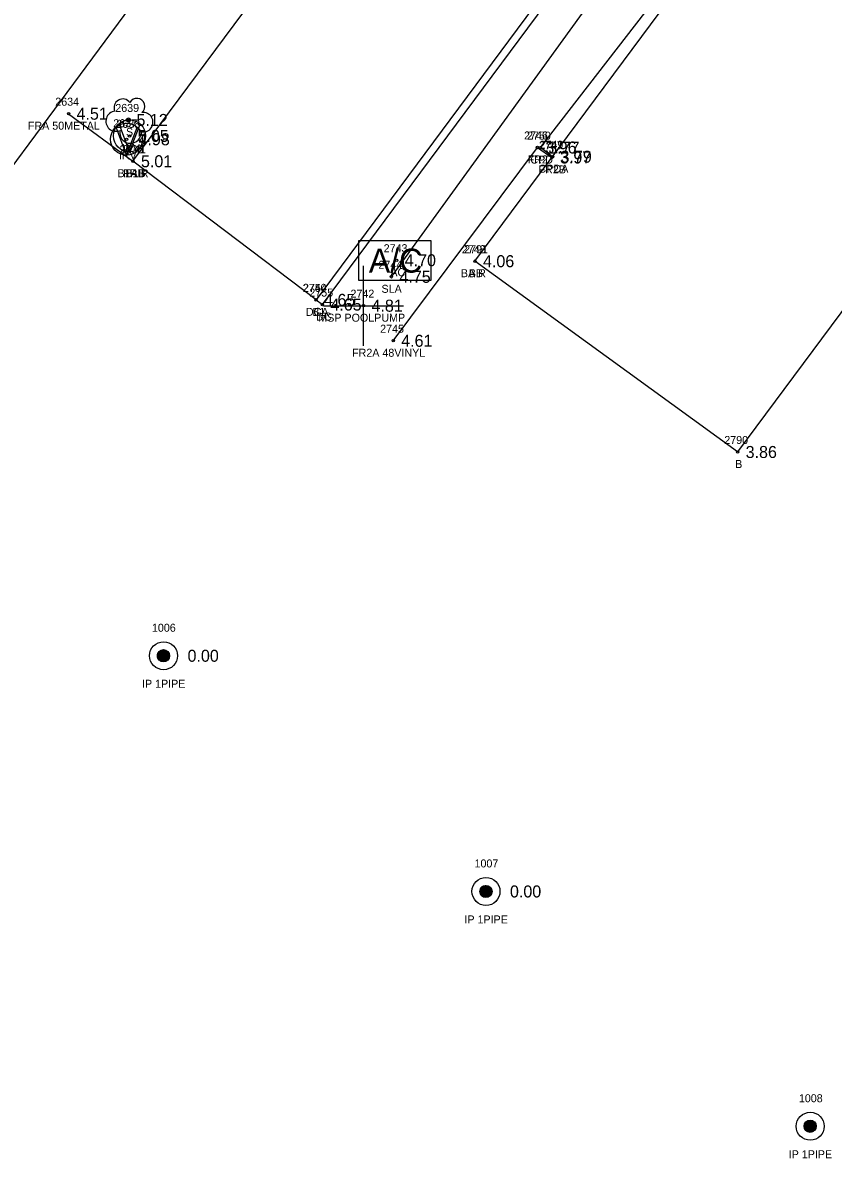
# Model space of a CAD drawing. Extents: x 2608598 to 2610682, y 641451 to 643526.
# Drawn here: x 2610061 to 2610162.3, y 641830.4 to 641972.3 of the extents above; entities that cross this region are included whole.
import ezdxf

# ---------------------------------------------------------------- set-up
doc = ezdxf.new("R2010")
doc.units = 0
for name, color, linetype in [('RD_EX_Bldg', 7, 'Continuous'), ('RD_EX_Bldg_txCode', 7, 'Continuous'), ('RD_EX_BldgApp', 7, 'Continuous'), ('RD_EX_BldgApp_txCode', 7, 'Continuous'), ('RD_EX_Conc', 7, 'Continuous'), ('RD_EX_Conc_txCode', 7, 'Continuous'), ('RD_EX_DV_Prop_txCode', 7, 'Continuous'), ('RD_EX_DV_PropPin', 7, 'Continuous'), ('RD_EX_Fence_Other', 7, 'Continuous'), ('RD_EX_Fence_Other_txCode', 7, 'Continuous'), ('RD_EX_Misc', 7, 'Continuous'), ('RD_EX_Misc_txCode', 7, 'Continuous'), ('RD_EX_TX_Bldg_ELEV', 7, 'Continuous'), ('RD_EX_TX_BldgApp_ELEV', 7, 'Continuous'), ('RD_EX_TX_Conc_ELEV', 7, 'Continuous'), ('RD_EX_TX_DV_Prop_ELEV', 7, 'Continuous'), ('RD_EX_TX_Fence_Other_ELEV', 7, 'Continuous'), ('RD_EX_TX_Misc_ELEV', 7, 'Continuous'), ('RD_EX_TX_UT_ELEV', 7, 'Continuous'), ('RD_EX_TX_VEG_ELEV', 7, 'Continuous'), ('RD_EX_UT', 7, 'Continuous'), ('RD_EX_UT_txCode', 7, 'Continuous'), ('RD_EX_VEG', 7, 'Continuous'), ('RD_EX_VEG_txCode', 7, 'Continuous'), ('RD_SMD_Locator', 7, 'Continuous')]:
    doc.layers.add(name, color=color, linetype=linetype)

msp = doc.modelspace()

# ---------------------------------------------------------------- linework, layer by layer
at = {"layer": 'RD_EX_Bldg'}
for points in [[(2610074.75, 641955.02), (2610121.89, 642018.49), (2610144.77, 642001.17), (2610097.63, 641937.7), (2610074.75, 641955.02)], [(2610117.49, 641942.53), (2610163.78, 642004.89), (2610174.8, 641996.67), (2610165.23, 641983.77), (2610177.63, 641974.57), (2610167.76, 641961.77), (2610177.2, 641954.91), (2610150.31, 641918.69), (2610117.49, 641942.53)], [(2610055.59, 641998.42), (2610028.78, 641961.42), (2610024.2, 641964.93), (2610014.46, 641951.93), (2610030.09, 641940.65), (2610042.73, 641931.52), (2610079.25, 641980.82), (2610055.59, 641998.42)]]:
    msp.add_lwpolyline(points, dxfattribs=at)
at = {"layer": 'RD_EX_BldgApp'}
for q in [(2610072.64, 641959.26), (2610075.27, 641959.22)]:
    msp.add_line((2610073.95, 641955.77), q, dxfattribs=at)
msp.add_lwpolyline([(2610102.97, 641940.1), (2610102.97, 641945.1), (2610111.97, 641945.1), (2610111.97, 641940.1)], close=True, dxfattribs=at)
for radius in [2, 0.15]:
    msp.add_circle((2610073.95, 641957.77), radius, dxfattribs=at)
at = {"layer": 'RD_EX_Conc'}
for points in [[(2610097.63, 641937.7), (2610098.42, 641937.11), (2610146.5, 642001.85), (2610145.19, 642002.76), (2610160.49, 642023.46), (2610172.05, 642039.3)], [(2610127.18, 641955.59), (2610125.66, 641956.72), (2610143.6, 641979.88), (2610144.54, 641978.98)]]:
    msp.add_lwpolyline(points, dxfattribs=at)
at = {"layer": 'RD_EX_DV_PropPin'}
for p, q in [((2610077.83, 641893.03), (2610077.83, 641893.42)), ((2610077.87, 641892.93), (2610077.87, 641893.52)), ((2610077.9, 641892.86), (2610077.9, 641893.6)), ((2610077.94, 641892.8), (2610077.94, 641893.65)), ((2610077.97, 641892.75), (2610077.97, 641893.7)), ((2610078.01, 641892.71), (2610078.01, 641893.74)), ((2610078.04, 641892.68), (2610078.04, 641893.78)), ((2610078.08, 641892.64), (2610078.08, 641893.81)), ((2610078.11, 641892.62), (2610078.11, 641893.84)), ((2610078.15, 641892.59), (2610078.15, 641893.86)), ((2610078.18, 641892.57), (2610078.18, 641893.88)), ((2610078.22, 641892.55), (2610078.22, 641893.9)), ((2610078.25, 641892.53), (2610078.25, 641893.92)), ((2610078.29, 641892.52), (2610078.29, 641893.93)), ((2610078.32, 641892.51), (2610078.32, 641893.95)), ((2610078.36, 641892.49), (2610078.36, 641893.96)), ((2610078.39, 641892.49), (2610078.39, 641893.97)), ((2610078.43, 641892.48), (2610078.43, 641893.97)), ((2610078.46, 641892.47), (2610078.46, 641893.98)), ((2610078.5, 641892.47), (2610078.5, 641893.98)), ((2610078.53, 641892.47), (2610078.53, 641893.99)), ((2610078.57, 641892.47), (2610078.57, 641893.99)), ((2610078.6, 641892.47), (2610078.6, 641893.99)), ((2610078.64, 641892.47), (2610078.64, 641893.98)), ((2610078.67, 641892.47), (2610078.67, 641893.98)), ((2610078.71, 641892.48), (2610078.71, 641893.97)), ((2610078.74, 641892.49), (2610078.74, 641893.97)), ((2610078.78, 641892.49), (2610078.78, 641893.96)), ((2610078.81, 641892.51), (2610078.81, 641893.95)), ((2610078.85, 641892.52), (2610078.85, 641893.93)), ((2610078.88, 641892.53), (2610078.88, 641893.92)), ((2610078.92, 641892.55), (2610078.92, 641893.9)), ((2610078.95, 641892.57), (2610078.95, 641893.88)), ((2610078.99, 641892.59), (2610078.99, 641893.86)), ((2610079.02, 641892.62), (2610079.02, 641893.84)), ((2610079.06, 641892.64), (2610079.06, 641893.81)), ((2610079.09, 641892.68), (2610079.09, 641893.78)), ((2610079.13, 641892.71), (2610079.13, 641893.74)), ((2610079.16, 641892.75), (2610079.16, 641893.7)), ((2610079.2, 641892.8), (2610079.2, 641893.65)), ((2610079.23, 641892.86), (2610079.23, 641893.6)), ((2610079.27, 641892.93), (2610079.27, 641893.52)), ((2610079.3, 641893.03), (2610079.3, 641893.42)), ((2610118.68, 641863.04), (2610118.68, 641864.53)), ((2610118.72, 641863.04), (2610118.72, 641864.53)), ((2610118.75, 641863.03), (2610118.75, 641864.54)), ((2610118.79, 641863.03), (2610118.79, 641864.54)), ((2610118.82, 641863.02), (2610118.82, 641864.54)), ((2610118.86, 641863.02), (2610118.86, 641864.55)), ((2610118.89, 641863.02), (2610118.89, 641864.54)), ((2610118.93, 641863.03), (2610118.93, 641864.54)), ((2610118.96, 641863.03), (2610118.96, 641864.54)), ((2610119, 641863.04), (2610119, 641864.53)), ((2610119.03, 641863.04), (2610119.03, 641864.53)), ((2610118.12, 641863.59), (2610118.12, 641863.98)), ((2610118.16, 641863.49), (2610118.16, 641864.08)), ((2610118.19, 641863.42), (2610118.19, 641864.15)), ((2610118.23, 641863.36), (2610118.23, 641864.21)), ((2610118.26, 641863.31), (2610118.26, 641864.26)), ((2610118.3, 641863.27), (2610118.3, 641864.3)), ((2610118.33, 641863.23), (2610118.33, 641864.34)), ((2610118.37, 641863.2), (2610118.37, 641864.37)), ((2610118.4, 641863.17), (2610118.4, 641864.39)), ((2610118.44, 641863.15), (2610118.44, 641864.42)), ((2610118.47, 641863.13), (2610118.47, 641864.44)), ((2610118.51, 641863.11), (2610118.51, 641864.46)), ((2610118.54, 641863.09), (2610118.54, 641864.48)), ((2610118.58, 641863.08), (2610118.58, 641864.49)), ((2610118.61, 641863.06), (2610118.61, 641864.51)), ((2610118.65, 641863.05), (2610118.65, 641864.52)), ((2610119.07, 641863.05), (2610119.07, 641864.52)), ((2610119.1, 641863.06), (2610119.1, 641864.51)), ((2610119.14, 641863.08), (2610119.14, 641864.49)), ((2610119.17, 641863.09), (2610119.17, 641864.48)), ((2610119.21, 641863.11), (2610119.21, 641864.46)), ((2610119.24, 641863.13), (2610119.24, 641864.44)), ((2610119.28, 641863.15), (2610119.28, 641864.42)), ((2610119.31, 641863.17), (2610119.31, 641864.39)), ((2610119.35, 641863.2), (2610119.35, 641864.37)), ((2610119.38, 641863.23), (2610119.38, 641864.34)), ((2610119.42, 641863.27), (2610119.42, 641864.3)), ((2610119.45, 641863.31), (2610119.45, 641864.26)), ((2610119.49, 641863.36), (2610119.49, 641864.21)), ((2610119.52, 641863.42), (2610119.52, 641864.15)), ((2610119.56, 641863.49), (2610119.56, 641864.08)), ((2610119.59, 641863.59), (2610119.59, 641863.98)), ((2610158.68, 641834.14), (2610158.68, 641834.73)), ((2610158.72, 641834.07), (2610158.72, 641834.81)), ((2610158.75, 641834.01), (2610158.75, 641834.86)), ((2610158.79, 641833.96), (2610158.79, 641834.91)), ((2610158.82, 641833.92), (2610158.82, 641834.95)), ((2610158.86, 641833.89), (2610158.86, 641834.99)), ((2610158.89, 641833.85), (2610158.89, 641835.02)), ((2610158.93, 641833.83), (2610158.93, 641835.05)), ((2610158.96, 641833.8), (2610158.96, 641835.07)), ((2610159, 641833.78), (2610159, 641835.09)), ((2610159.03, 641833.76), (2610159.03, 641835.11)), ((2610159.07, 641833.74), (2610159.07, 641835.13)), ((2610159.1, 641833.73), (2610159.1, 641835.14)), ((2610159.14, 641833.72), (2610159.14, 641835.16)), ((2610159.17, 641833.7), (2610159.17, 641835.17)), ((2610159.21, 641833.7), (2610159.21, 641835.18)), ((2610159.24, 641833.69), (2610159.24, 641835.18)), ((2610159.28, 641833.68), (2610159.28, 641835.19)), ((2610159.31, 641833.68), (2610159.31, 641835.19)), ((2610159.35, 641833.68), (2610159.35, 641835.2)), ((2610159.38, 641833.68), (2610159.38, 641835.2)), ((2610159.42, 641833.68), (2610159.42, 641835.2)), ((2610159.45, 641833.68), (2610159.45, 641835.19)), ((2610159.49, 641833.68), (2610159.49, 641835.19)), ((2610159.52, 641833.69), (2610159.52, 641835.18)), ((2610159.56, 641833.7), (2610159.56, 641835.18)), ((2610159.59, 641833.7), (2610159.59, 641835.17)), ((2610159.63, 641833.72), (2610159.63, 641835.16)), ((2610159.66, 641833.73), (2610159.66, 641835.14)), ((2610159.7, 641833.74), (2610159.7, 641835.13)), ((2610159.73, 641833.76), (2610159.73, 641835.11)), ((2610159.77, 641833.78), (2610159.77, 641835.09)), ((2610159.8, 641833.8), (2610159.8, 641835.07)), ((2610159.84, 641833.83), (2610159.84, 641835.05)), ((2610159.87, 641833.85), (2610159.87, 641835.02)), ((2610159.91, 641833.89), (2610159.91, 641834.99)), ((2610159.94, 641833.92), (2610159.94, 641834.95)), ((2610159.98, 641833.96), (2610159.98, 641834.91)), ((2610160.01, 641834.01), (2610160.01, 641834.86)), ((2610160.05, 641834.07), (2610160.05, 641834.81)), ((2610160.08, 641834.14), (2610160.08, 641834.73)), ((2610158.65, 641834.24), (2610158.65, 641834.63)), ((2610160.12, 641834.24), (2610160.12, 641834.63))]:
    msp.add_line(p, q, dxfattribs=at)
for centre, radius in [((2610078.57, 641893.23), 1.75), ((2610078.57, 641893.23), 0.761), ((2610118.86, 641863.78), 1.75), ((2610118.86, 641863.78), 0.761), ((2610159.38, 641834.44), 1.75), ((2610159.38, 641834.44), 0.761)]:
    msp.add_circle(centre, radius, dxfattribs=at)
at = {"layer": 'RD_EX_Fence_Other'}
msp.add_line((2610066.7, 641960.96), (2610074.75, 641955.02), dxfattribs=at)
msp.add_lwpolyline([(2610107.27, 641932.59), (2610125.28, 641956.74), (2610127.11, 641955.49)], dxfattribs=at)
at = {"layer": 'RD_EX_Misc'}
for p, q in [((2610103.56, 641931.97), (2610103.56, 641941.97)), ((2610098.56, 641936.97), (2610108.56, 641936.97))]:
    msp.add_line(p, q, dxfattribs=at)
at = {"layer": 'RD_EX_UT'}
for q in [(2610073.02, 641959.68), (2610075.65, 641959.64)]:
    msp.add_line((2610074.32, 641956.19), q, dxfattribs=at)
msp.add_circle((2610074.32, 641958.19), 2, dxfattribs=at)
at = {"layer": 'RD_EX_VEG'}
msp.add_line((2610107.05, 641940.58), (2610145.08, 641993.08), dxfattribs=at)
msp.add_circle((2610074.19, 641960.18), 0.25, dxfattribs=at)
for centre, radius, start, end in [((2610073.47, 641961.72), 1.08, 34.9763, 204.756), ((2610075.24, 641961.88), 0.995, 308.7626, 152.0467), ((2610072.63, 641960.02), 1.26, 96.4518, 294.734), ((2610076.03, 641959.9), 1.22, 256.5667, 98.1046), ((2610074.44, 641958.58), 1.32, 166.8827, 5.7589)]:
    msp.add_arc(centre, radius, start, end, dxfattribs=at)
at = {"layer": 'RD_SMD_Locator'}
for centre in [(2610066.7, 641960.96), (2610074.19, 641960.18), (2610074.32, 641958.19), (2610125.28, 641956.74), (2610125.66, 641956.72), (2610127.11, 641955.49), (2610127.18, 641955.59), (2610074.75, 641955.02), (2610074.75, 641955.02), (2610074.75, 641955.02), (2610107.71, 641942.65), (2610117.49, 641942.53), (2610117.49, 641942.53), (2610107.05, 641940.58), (2610097.63, 641937.7), (2610097.63, 641937.7), (2610098.42, 641937.11), (2610103.56, 641936.97), (2610107.27, 641932.59), (2610150.31, 641918.69), (2610078.57, 641893.23), (2610118.86, 641863.78), (2610159.38, 641834.44)]:
    msp.add_circle(centre, 0.15, dxfattribs=at)

# ---------------------------------------------------------------- texts
at = {"layer": 'RD_EX_Bldg_txCode'}
for s, p in [('2636', (2610073.07, 641956.02)), ('2741', (2610073.4, 641956.02)), ('B1A R', (2610072.83, 641953.02)), ('B1B', (2610073.8, 641953.02)), ('2748', (2610115.86, 641943.53)), ('2791', (2610116.14, 641943.53)), ('BA R', (2610115.73, 641940.53)), ('BB', (2610116.71, 641940.53)), ('2740', (2610095.96, 641938.7)), ('B1', (2610097.16, 641935.7)), ('2790', (2610148.64, 641919.69)), ('B', (2610150, 641916.69))]:
    msp.add_text(s, height=1, dxfattribs=at).set_placement(p)
at = {"layer": 'RD_EX_BldgApp'}
msp.add_text('A/C', height=3, dxfattribs=at).set_placement((2610104.22, 641941.1))
at = {"layer": 'RD_EX_BldgApp_txCode'}
for s, p in [('2743', (2610106.08, 641943.65)), ('AC', (2610106.91, 641940.65))]:
    msp.add_text(s, height=1, dxfattribs=at).set_placement(p)
at = {"layer": 'RD_EX_Conc_txCode'}
for s, p in [('2750', (2610123.99, 641957.72)), ('2749', (2610125.55, 641956.59)), ('CPD', (2610124.41, 641954.72)), ('CPDA', (2610125.44, 641953.59)), ('2754', (2610096, 641938.7)), ('2755', (2610096.79, 641938.11)), ('DCA', (2610096.36, 641935.7)), ('DC', (2610097.64, 641935.11))]:
    msp.add_text(s, height=1, dxfattribs=at).set_placement(p)
at = {"layer": 'RD_EX_DV_Prop_txCode'}
for s, p in [('1006', (2610077.12, 641896.23)), ('IP 1PIPE', (2610075.88, 641889.23)), ('1007', (2610117.43, 641866.78)), ('IP 1PIPE', (2610116.17, 641859.78)), ('1008', (2610157.96, 641837.44)), ('IP 1PIPE', (2610156.69, 641830.44))]:
    msp.add_text(s, height=1, dxfattribs=at).set_placement(p)
at = {"layer": 'RD_EX_Fence_Other_txCode'}
for s, p in [('2634', (2610065.04, 641961.96)), ('FRA 50METAL', (2610061.62, 641958.96)), ('2746', (2610123.62, 641957.74)), ('2635', (2610073.1, 641956.02)), ('2747', (2610125.48, 641956.49)), ('FR2', (2610124.07, 641954.74)), ('FRB', (2610073.52, 641953.02)), ('FR2B', (2610125.43, 641953.49)), ('2745', (2610105.64, 641933.59)), ('FR2A 48VINYL', (2610102.13, 641930.59))]:
    msp.add_text(s, height=1, dxfattribs=at).set_placement(p)
at = {"layer": 'RD_EX_Misc_txCode'}
for s, p in [('2637', (2610072.29, 641959.27)), ('IRV', (2610072.99, 641955.27)), ('2742', (2610101.93, 641937.97)), ('MSP POOLPUMP', (2610097.91, 641934.97))]:
    msp.add_text(s, height=1, dxfattribs=at).set_placement(p)
at = {"layer": 'RD_EX_TX_Bldg_ELEV'}
for s, p in [('5.01', (2610075.75, 641954.27)), ('5.01', (2610075.75, 641954.27)), ('4.06', (2610118.49, 641941.78)), ('4.06', (2610118.49, 641941.78)), ('4.65', (2610098.63, 641936.95)), ('3.86', (2610151.31, 641917.94))]:
    msp.add_text(s, height=1.5, dxfattribs=at).set_placement(p)
at = {"layer": 'RD_EX_TX_BldgApp_ELEV'}
msp.add_text('4.70', height=1.5, dxfattribs=at).set_placement((2610108.71, 641941.9))
at = {"layer": 'RD_EX_TX_Conc_ELEV'}
for s, p in [('3.77', (2610126.66, 641955.97)), ('3.79', (2610128.18, 641954.84)), ('4.65', (2610098.63, 641936.95)), ('4.65', (2610099.42, 641936.36))]:
    msp.add_text(s, height=1.5, dxfattribs=at).set_placement(p)
at = {"layer": 'RD_EX_TX_DV_Prop_ELEV'}
for p in [(2610081.57, 641892.48), (2610121.86, 641863.03)]:
    msp.add_text('0.00', height=1.5, dxfattribs=at).set_placement(p)
at = {"layer": 'RD_EX_TX_Fence_Other_ELEV'}
for s, p in [('4.51', (2610067.7, 641960.21)), ('3.96', (2610126.28, 641955.99)), ('5.01', (2610075.75, 641954.27)), ('3.97', (2610128.11, 641954.74)), ('4.61', (2610108.27, 641931.84))]:
    msp.add_text(s, height=1.5, dxfattribs=at).set_placement(p)
at = {"layer": 'RD_EX_TX_Misc_ELEV'}
for s, p in [('4.98', (2610075.45, 641957.02)), ('4.81', (2610104.56, 641936.22))]:
    msp.add_text(s, height=1.5, dxfattribs=at).set_placement(p)
at = {"layer": 'RD_EX_TX_UT_ELEV'}
msp.add_text('5.05', height=1.5, dxfattribs=at).set_placement((2610075.32, 641957.44))
at = {"layer": 'RD_EX_TX_VEG_ELEV'}
for s, p in [('5.12', (2610075.19, 641959.43)), ('4.75', (2610108.05, 641939.83))]:
    msp.add_text(s, height=1.5, dxfattribs=at).set_placement(p)
at = {"layer": 'RD_EX_UT_txCode'}
for s, p in [('2638', (2610072.67, 641959.19)), ('WV', (2610073.46, 641956.19))]:
    msp.add_text(s, height=1, dxfattribs=at).set_placement(p)
at = {"layer": 'RD_EX_VEG_txCode'}
for s, p in [('2639', (2610072.54, 641961.18)), ('S', (2610073.88, 641958.18)), ('2744', (2610105.42, 641941.58)), ('SLA', (2610105.81, 641938.58))]:
    msp.add_text(s, height=1, dxfattribs=at).set_placement(p)

doc.saveas('drawing.dxf')
